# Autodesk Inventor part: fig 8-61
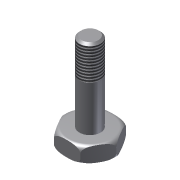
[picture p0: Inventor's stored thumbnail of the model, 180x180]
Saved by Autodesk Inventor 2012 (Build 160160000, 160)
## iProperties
Shininess: 77.0
Length Units: 11269
Angle Units: 11279
Time Units: 11290
Mass Units: 11283
Length Display Precision: 3
Angle Display Precision: 2
Created: 2002-01
Part Number: fig 8-61
Document SubType Name: Modeling
Designer: ***
Density: 1 g/cm^3
Material: Default
Density: 0.0
Volumn: 0.0
Area: 0.0
PropertySet Name: Model Information
Control State: 0
Master: False
Checked Out: False
Author: ***
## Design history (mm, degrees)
sketch "Sketch1"
  geometry: C1 r 25 at (0, 0)
  constraints: 1 centre point
  dimensions: "d0" = 50 diameter of C1
extrude "Extrusion1" new body sketch "Sketch1" distance "d1" = 15; taper "d2" = 0 deg
fillet "Fillet1" dims "d3" = 5
sketch "Sketch2"
  geometry: L1 (25.058, 0)-(12.529, -21.701); L2 (12.529, -21.701)-(-12.529, -21.701); L3 (-12.529, -21.701)-(-25.058, 0); L4 (-25.058, 0)-(-12.529, 21.701); L5 (-12.529, 21.701)-(12.529, 21.701); L6 (12.529, 21.701)-(25.058, 0); 1 further point
  constraints: 12 end point, 11 other
extrude "Extrusion2" sketch "Sketch2" stored distance "d4" = 15; taper "d5" = 0 deg
sketch "Sketch3"
  geometry: C1 r 10.044 at (0, 0); 1 further point
  constraints: 1 centre point, 1 coincident
extrude "Extrusion3" join sketch "Sketch3" distance "d6" = 75; taper "d7" = 0 deg
chamfer "Chamfer1" distance "d8" = 2; stored, may be unused: second distance "d9" = 2, angle "d16" = 45 deg
thread "Thread3" dims "d14" = 30, "d15" = 0
body "Solid1"
